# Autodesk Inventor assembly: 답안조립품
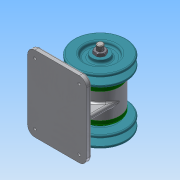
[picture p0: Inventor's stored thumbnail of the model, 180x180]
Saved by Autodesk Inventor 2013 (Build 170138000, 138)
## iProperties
Created: 2019-09
Part Number: 답안조립품
Document SubType Name: Assembly
Designer: Administrator
Author: Administrator
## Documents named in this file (10)
- C:\Users\Administrator\Desktop\490904V1053\답안조립품.iam
- C:\Users\Administrator\Desktop\490904V1053\본체.ipt
- C:\Users\Administrator\Desktop\490904V1053\V-벨트풀리.ipt
- C:\Users\Administrator\Desktop\490904V1053\너트 M10x1.ipt
- C:\Users\Administrator\Desktop\490904V1053\베어링 6004.ipt
- C:\Users\Administrator\Desktop\490904V1053\볼트 M4.ipt
- C:\Users\Administrator\Desktop\490904V1053\오일 실 17 30 5.ipt
- C:\Users\Administrator\Desktop\490904V1053\축.ipt
- C:\Users\Administrator\Desktop\490904V1053\커버.ipt
- C:\Users\Administrator\Desktop\490904V1053\키 5 x 5 x 12.ipt
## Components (2 placed, 1 different names)
1. V-벨트풀리:1
2. V-벨트풀리:2
